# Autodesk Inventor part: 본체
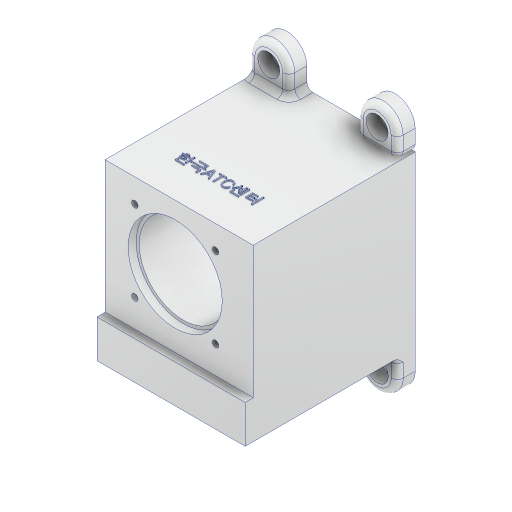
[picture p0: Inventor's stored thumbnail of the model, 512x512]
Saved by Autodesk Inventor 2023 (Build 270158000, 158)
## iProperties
Created: 2024-11
Part Number: 본체
Material: 알루미늄 6061
Document SubType Name: Modeling
Designer: home
Density: 2.7 g/cm^3
Appearance: 알루미늄 - 평지
Mass: 1097.44 g
Surface Area: 539.9 cm^2
Volume: 406.46 cm^3
Author: home
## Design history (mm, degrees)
sketch "스케치10"
  geometry: L1 (-37, 42.5)-(37, 42.5); L2 (37, 42.5)-(37, -42.5); L3 (37, -42.5)-(-37, -42.5); L4 (-37, -42.5)-(-37, 42.5); L5 (-37, 42.5)-(37, -42.5); L6 (37, 42.5)-(-37, -42.5); 1 further point
  constraints: 12 end point, 2 midpoint, 2 parallel, 1 horizontal, 1 perpendicular
  dimensions: "d43" = 74 distance of L1.start L1.end; "d44" = 85 distance of L3.end L1.start
extrude "돌출8" new body sketch "스케치10" stored distance "d45" = 85; taper "d46" = 0 deg
sketch "스케치11"
  geometry: L1 (85, 85)-(0, 85) reference; L2 (0, 0)-(0, 85) reference; L3 (0, 85)-(4, 85); L4 (4, 85)-(4, 19); L5 (4, 19)-(0, 19); L6 (0, 19)-(0, 85); L7 (0, 85)-(4, 19); L8 (4, 85)-(0, 19); 4 further points
  constraints: 12 end point, 2 midpoint, 2 parallel, 1 horizontal, 1 perpendicular
  dimensions: "d47" = 4 distance of L1.end L3.end; "d48" = 66 distance of L3.end L4.end
extrude "돌출9" cut sketch "스케치11" distance "d49" = 77; taper "d50" = 0 deg
sketch "스케치31"
  geometry: C1 r 23.5 at (35.036, 34.068); 1 further point
  constraints: 1 centre point
  dimensions: "d164" = 47 diameter of C1
extrude "돌출21" cut sketch "스케치31" distance "d165" = 4; taper "d166" = 0 deg
sketch "스케치32"
  geometry: C1 r 23.5 at (0, 0) reference; C2 r 22 at (0, 0); 1 further point
  constraints: 1 centre point, 1 coincident
  dimensions: "d168" = 44 diameter of C2
extrude "돌출22" cut sketch "스케치32" distance "d169" = 40; taper "d170" = 0 deg
sketch "스케치35"
  geometry: C1 r 22 at (0, 0) reference; C2 r 17.5 at (0, 0); 1 further point
  constraints: 1 centre point, 1 coincident
  dimensions: "d175" = 35 diameter of C2
extrude "돌출24" cut sketch "스케치35" distance "d176" = 11; taper "d177" = 0 deg
sketch "스케치38"
  geometry: L1 (37, -42.5)-(37, 42.5) reference; L2 (-16.907, 52.568)-(-16.907, 42.568); L3 (-16.907, 42.568)-(-36.907, 42.568); L4 (-36.907, 42.568)-(-36.907, 52.568); L5 (-16.907, 62.568)-(-36.907, 42.568); L6 (-36.907, 62.568)-(-26.907, 52.568); L7 (-19.836, 45.497)-(-16.907, 42.568); L8 (37, 42.5)-(-37, 42.5) reference; L9 (37, 62.5)-(37.204, 62.5); L10 (37.204, 52.5)-(37.204, 42.5); L11 (37.204, 42.5)-(17.204, 42.5); L12 (17.204, 42.5)-(17.204, 52.5); L13 (17.204, 62.5)-(37.204, 42.5); L14 (37.204, 62.5)-(17.204, 42.5); A1 r 10 centre (-26.907, 52.568) between (-16.907, 52.568) and (-36.907, 52.568); A2 r 10 centre (27.204, 52.5) between (37.204, 52.5) and (17.204, 52.5); A3 r 10 centre (27.204, 52.5) between (26.037, 42.568) and (27.204, 42.5); 4 further points
  constraints: 24 end point, 6 point on circle, 5 midpoint, 3 centre point, 3 parallel, 3 point on line, 2 coincident, 1 horizontal, 1 perpendicular
  dimensions: "d194" = 20 distance of L6.start L5.start; "d195" = 20 distance of L5.start L2.end; "d196" = 20 diameter of A1; "d197" = 20 distance of L13.start L9.end; "d198" = 20 distance of L9.end L10.end
sketch "스케치36"
  geometry: C1 r 17.5 at (0, 0) reference; C2 r 15 at (0, 0); 1 further point
  constraints: 1 centre point, 1 coincident
  dimensions: "d178" = 30 diameter of C2
extrude "돌출25" cut sketch "스케치36" distance "d179" = 4; taper "d180" = 0 deg
sketch "스케치37"
  geometry: L1 (35.036, 62.568)-(35.036, 5.568); L2 (35.036, 34.068)-(14.884, 54.22); L3 (35.036, 34.068)-(55.189, 54.22); L4 (35.036, 34.068)-(14.884, 13.915); L5 (35.036, 34.068)-(55.624, 13.48); C1 r 23.5 at (35.036, 34.068) reference; A1 r 28.5 centre (35.036, 34.068) between (35.036, 62.568) and (35.036, 5.568); 5 further points
  constraints: 10 end point, 6 point on circle, 4 coincident, 1 centre point, 1 point on line, 1 vertical
  dimensions: "d181" = 57 diameter of A1; "d182" = 45 deg angle of L1 L2; "d183" = 45 deg angle of L3 L1; "d184" = 90 deg angle of L5 L4; "d185" = 45 deg angle of L1 L4
hole "구멍8" sketch "스케치37" at (14.884, 54.22), (55.189, 54.22), (14.884, 13.915), (55.189, 13.915) diameter "d186" = 3.242; stored, may be unused: countersink angle "d190" = 90 deg, drill point angle "d192" = 118 deg; dims "d187" = 8, "d188" = 4, "d189" = 2, "d191" = 10
extrude "돌출26" join sketch "스케치38" distance "d200" = 9; taper "d201" = 0 deg
sketch "스케치39"
  geometry: A1 r 10 centre (26.907, 52.568) between (36.907, 52.568) and (16.907, 52.568) reference; 2 further points
  constraints: 1 coincident
sketch "스케치40"
  geometry: A1 r 10 centre (-27.204, 52.5) between (-17.204, 52.5) and (-37.204, 52.5) reference; 2 further points
  constraints: 1 coincident
hole "구멍9" sketch "스케치40" at (-27.204, 52.5) diameter "d202" = 3.242; stored, may be unused: countersink angle "d206" = 90 deg, drill point angle "d208" = 0 deg; dims "d203" = 8, "d204" = 11, "d205" = 6.6, "d207" = 6.6
hole "구멍10" sketch "스케치39" diameter "d209" = 3.242; stored, may be unused: countersink angle "d213" = 90 deg, drill point angle "d215" = 0 deg; dims "d210" = 8, "d211" = 11, "d212" = 6.6, "d214" = 6.6
fillet "모깎기11" dims "d216" = 3
sketch "스케치45"
  geometry: 3 further points
  constraints: 1 vertical alignment, 1 other
  dimensions: "d242" = 20 vertical distance of point (74, 0) point (37, 20)
feature "엠보싱3" sketch "스케치45" dims "d43" = 74, "d44" = 85, "d243" = 0.5, "d244" = 0
sketch "스케치46"
  geometry: L1 (-37, -42.5)-(37, -42.5) reference; L2 (17.204, 52.5)-(17.204, 42.5) reference; L3 (37, -42.5)-(-37, -42.5) reference; L4 (17.204, -62.5)-(17, -62.5); L5 (17, -52.5)-(17, -42.5); L6 (17, -42.5)-(37, -42.5); L7 (37, -42.5)-(37, -52.5); L8 (17, -62.5)-(37, -42.5); L9 (37, -62.5)-(27, -52.5); L10 (19.929, -45.429)-(17, -42.5); L11 (-37, -52.5)-(-37, -42.5); L12 (-37, -42.5)-(-17, -42.5); L13 (-17, -42.5)-(-17, -52.5); L14 (-17, -62.5)-(-37, -42.5); L15 (-37, -62.5)-(-17, -42.5); A1 r 10 centre (27, -52.5) between (17, -52.5) and (37, -52.5); A2 r 10 centre (-27, -52.5) between (-37, -52.5) and (-17, -52.5); 4 further points
  constraints: 24 end point, 4 midpoint, 4 point on circle, 3 parallel, 2 centre point, 2 coincident, 2 point on line, 1 horizontal, 1 perpendicular
  dimensions: "d249" = 20 distance of L9.start L4.end; "d250" = 20 distance of L4.end L5.end; "d251" = 20 diameter of A1; "d252" = 20 distance of L14.start L15.start; "d253" = 20 distance of L1.start L15.start; "d254" = 20 diameter of A2
extrude "돌출29" join sketch "스케치46" distance "d255" = 9; taper "d256" = 0 deg
sketch "스케치47"
  geometry: A1 r 10 centre (-27, -52.5) between (-37, -52.5) and (-17, -52.5) reference; 2 further points
  constraints: 1 coincident
sketch "스케치48"
  geometry: A1 r 10 centre (27, -52.5) between (17, -52.5) and (37, -52.5) reference; 2 further points
  constraints: 1 coincident
hole "구멍13" sketch "스케치48" at (27, -52.5) diameter "d257" = 3.242; stored, may be unused: countersink angle "d261" = 90 deg, drill point angle "d263" = 0 deg; dims "d258" = 8, "d259" = 11, "d260" = 6.6, "d262" = 6.6
hole "구멍14" sketch "스케치47" diameter "d264" = 3.242; stored, may be unused: countersink angle "d268" = 90 deg, drill point angle "d270" = 0 deg; dims "d265" = 8, "d266" = 11, "d267" = 6.6, "d269" = 6.6
fillet "모깎기13" dims "d271" = 3
fillet "모깎기14" dims "d272" = 3
fillet "모깎기15" dims "d273" = 3
node "솔리드3"
feature "A9D066F2-1C7D-4E18-AEED-F7BC21143FA4" dims "d186" = 3.242, "d187" = 8, "d188" = 4, "d189" = 2, "d190" = 90 deg, "d191" = 10, "d192" = 118 deg
